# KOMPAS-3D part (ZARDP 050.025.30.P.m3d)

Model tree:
1. Плоскость XY
2. Плоскость ZX
3. Плоскость ZY
4. Ось X
5. Ось Y
6. Ось Z
7. Начало координат
8. Булева операция:1
9. Булева операция:2
10. Булева операция:3
11. Булева операция:4
12. Булева операция:5
13. Булева операция:6
